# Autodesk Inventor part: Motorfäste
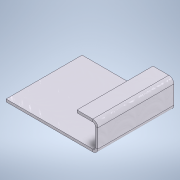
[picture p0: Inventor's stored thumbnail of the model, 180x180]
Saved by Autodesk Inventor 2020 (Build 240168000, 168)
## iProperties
Created: 2019-06
Part Number: Motorfäste
Material: Aluminum 6061, Welded
Document SubType Name: Sheet Metal
Designer: cl
Density: 2.7 g/cm^3
Sheet Metal Rule: Default_mm
Appearance: Weld - Aluminum
Author: cl
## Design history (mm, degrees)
node "Face1"
  sketch "Sketch2"
    geometry: L1 (0, 0)-(145, 0); L2 (145, 0)-(145, -120); L3 (145, -120)-(0, -120); L4 (0, -120)-(0, 0)
    constraints: 8 end point, 2 parallel, 1 horizontal, 1 perpendicular
    dimensions: "d4" = 145 distance of L2.end L3.end; "d5" = 120 distance of L1.end L2.end
node "Flange1"
node "Flange2"
body "Solid2"
face "Plate1" dims "d6" = 4 (= Thickness)
sketch "Sketch3"
  geometry: L1 through (0, 60) direction (0, -1); L2 through (22.5, 0) direction (1, 0); L3 (45, 0)-(45, 120); L4 (45, 120)-(0, 120)
  constraints: 6 end point, 1 horizontal, 1 perpendicular, 1 vertical
face "Plate2" dims "d6" = 4 (= Thickness), "d7" = 4 (= BendReliefWidth), "d8" = 2 (= BendReliefDepth), "d9" = 8 (= MinimumRemnant), "d10" = 4 (= TransitionRadius), "d11" = 45, "d12" = 90 deg, "d13" = 4 (= BendRadius), "d14" = 16 (= CornerReliefSize), "d15" = 4 (= GapSize), "d16" = 4 (= JacobiRadiusSize), "SeamGap" = 0.01
bend "Bend1" dims "d6" = 4 (= Thickness), "d7" = 4 (= BendReliefWidth), "d8" = 2 (= BendReliefDepth), "d9" = 8 (= MinimumRemnant), "d10" = 4 (= TransitionRadius), "d11" = 45, "d12" = 90 deg, "d13" = 4 (= BendRadius), "SeamGap" = 0.01
feature "Corner1" dims "d11" = 45, "d12" = 90 deg, "d14" = 16 (= CornerReliefSize), "d15" = 4 (= GapSize), "d16" = 4 (= JacobiRadiusSize)
sketch "Sketch4"
  geometry: L1 through (0, 60) direction (0, -1); L2 through (16.5, 0) direction (1, 2.48e-35); L3 (33, 0)-(33, 120); L4 (33, 120)-(0, 120)
  constraints: 6 end point, 1 horizontal, 1 perpendicular, 1 vertical
face "Plate3" dims "d6" = 4 (= Thickness), "d17" = 4 (= BendReliefWidth), "d18" = 2 (= BendReliefDepth), "d19" = 8 (= MinimumRemnant), "d20" = 4 (= TransitionRadius), "d21" = 33, "d22" = 90 deg, "d23" = 4 (= BendRadius), "d24" = 16 (= CornerReliefSize), "d25" = 4 (= GapSize), "d26" = 4 (= JacobiRadiusSize), "SeamGap" = 0.01
bend "Bend2" dims "d6" = 4 (= Thickness), "d17" = 4 (= BendReliefWidth), "d18" = 2 (= BendReliefDepth), "d19" = 8 (= MinimumRemnant), "d20" = 4 (= TransitionRadius), "d21" = 33, "d22" = 90 deg, "d23" = 4 (= BendRadius), "SeamGap" = 0.01
feature "Corner2" dims "d21" = 33, "d22" = 90 deg, "d24" = 16 (= CornerReliefSize), "d25" = 4 (= GapSize), "d26" = 4 (= JacobiRadiusSize)
other parameters: "Thickness" = 4 (derived), "KFactor" = 4.4, "BendRadius" = 4 (= Thickness), "BendReliefWidth" = 4 (= Thickness), "BendReliefDepth" = 2 (= 0.5 x Thickness), "CornerReliefSize" = 16 (= 4 x Thickness), "MinimumRemnant" = 8 (= 2 x Thickness), "TransitionRadius" = 4 (= BendRadius), "JacobiRadiusSize" = 4 (= BendRadius), "GapSize" = 4 (= Thickness)
